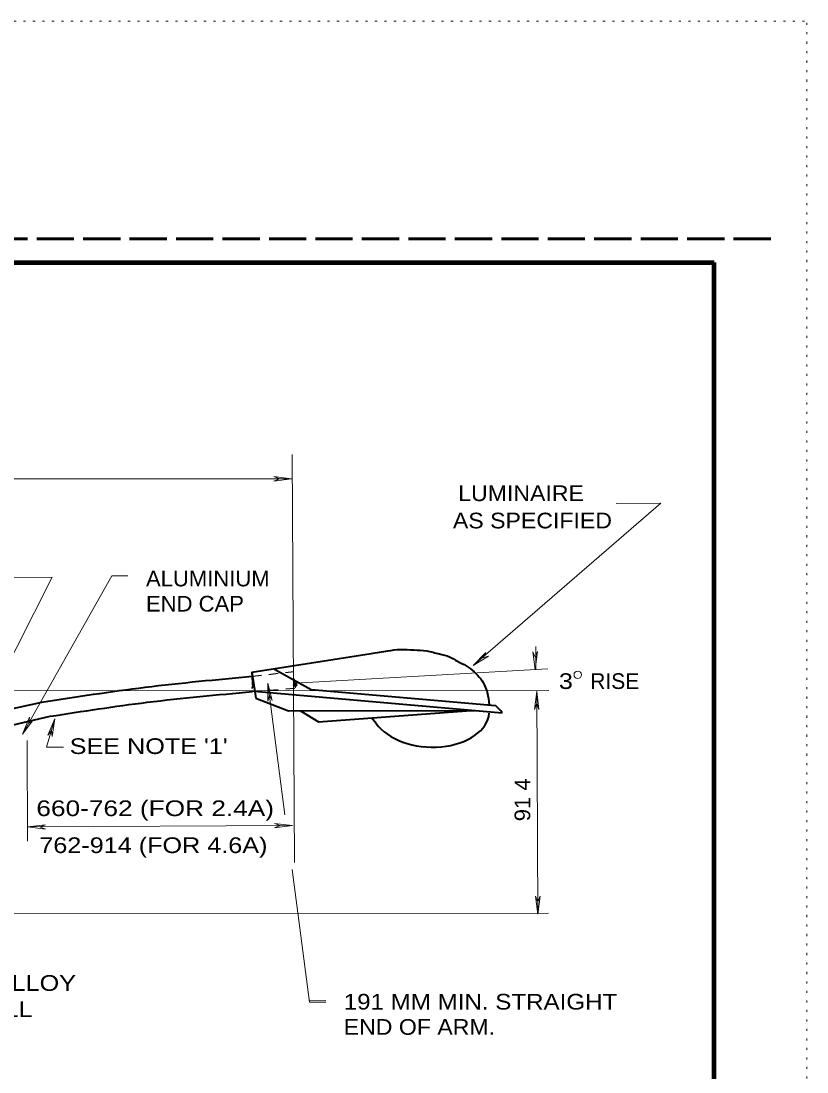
# Model space of a CAD drawing. Extents: x 312583 to 312854, y 144419 to 144597.
# Drawn here: x 312815.4 to 312853.5, y 144545.9 to 144596.8 of the extents above; entities that cross this region are included whole.
import ezdxf

# ---------------------------------------------------------------- set-up
doc = ezdxf.new("R2010")
doc.units = 0
doc.header["$LTSCALE"] = 0.3
doc.header["$PDMODE"] = 32
doc.header["$PDSIZE"] = 0.15
for name, pattern in [('DOTTED', [1.5, 0.3, -1.2]), ('LONG_DASHED', [7.5, 6, -1.5]), ('SHORT_DASHED', [2.7, 1.5, -1.2])]:
    doc.linetypes.add(name, pattern=pattern)
for name, color, linetype, lineweight in [('1', 7, 'Continuous', 35), ('2', 7, 'Continuous', 13), ('62', 7, 'DOTTED', 13), ('63', 7, 'LONG_DASHED', 60)]:
    doc.layers.add(name, color=color, linetype=linetype, lineweight=lineweight)

msp = doc.modelspace()

# ---------------------------------------------------------------- linework, layer by layer
at = {"layer": '1', "lineweight": 158}
msp.add_line((312849, 144423.1446), (312849, 144585.0846), dxfattribs=at)
at = {"layer": '1', "lineweight": 13}
msp.add_line((312840.3674, 144565.3613), (312840.3674, 144566.4806), dxfattribs=at)
at = {"layer": '1', "lineweight": 40}
for p, q in [((312826.6134, 144565.231), (312832.394, 144566.1356)), ((312826.6057, 144565.2233), (312826.6134, 144565.231)), ((312826.6134, 144565.231), (312826.667, 144564.495)), ((312826.6134, 144565.231), (312826.8127, 144563.966)), ((312827.7097, 144565.3843), (312829.4884, 144564.3876)), ((312826.6057, 144564.4873), (312826.667, 144564.495)), ((312829.4884, 144564.3876), (312838.4124, 144563.6133)), ((312826.7284, 144564.3033), (312838.742, 144563.2606)), ((312770.2404, 144553.754), (312816.4474, 144563.7743)), ((312813.166, 144562.2333), (312816.846, 144563.092))]:
    msp.add_line(p, q, dxfattribs=at)
at = {"layer": '1', "linetype": 'SHORT_DASHED', "lineweight": 25}
for p, q in [((312826.644, 144565.0316), (312828.645, 144565.2616)), ((312828.7294, 144564.4643), (312828.645, 144565.2616)), ((312826.644, 144564.288), (312828.7294, 144564.4643))]:
    msp.add_line(p, q, dxfattribs=at)
at = {"layer": '1', "lineweight": 158}
msp.add_lwpolyline([(312616.5, 144423.1446), (312616.5, 144585.0846), (312849, 144585.0846)], dxfattribs=at)
at = {"layer": '1', "lineweight": 40}
for points in [[(312826.8127, 144563.966), (312828.392, 144563.3526), (312837.408, 144563.3756)], [(312828.967, 144563.3526), (312829.8487, 144562.8313), (312837.017, 144563.3526)]]:
    msp.add_lwpolyline(points, dxfattribs=at)
msp.add_arc((312836.6357, 144561.6006), 2.6839, 38.22857, 48.47979, dxfattribs=at)
msp.add_ellipse((312835.2491, 144563.4306), major_axis=(-2.8667, 0.1434), ratio=0.637387, start_param=0.461652, end_param=3.1175647, dxfattribs=at)
for points in [[(312832.394, 144566.1356), (312833.2067, 144566.266), (312833.8047, 144566.335), (312834.464, 144566.312), (312835.085, 144566.266), (312835.6984, 144566.1126), (312836.189, 144565.9823), (312836.58, 144565.76), (312837.0017, 144565.5376), (312837.3774, 144565.254), (312837.707, 144564.9013), (312837.9064, 144564.5486), (312838.0137, 144564.2573), (312838.1134, 144563.644)], [(312816.4474, 144563.7743), (312821.4537, 144564.5026), (312826.644, 144565.0316)], [(312816.846, 144563.092), (312821.5534, 144563.7743), (312826.644, 144564.288)]]:
    msp.add_spline(points, degree=3, dxfattribs=at)
at = {"layer": '1'}
msp.add_point((312828.714, 144564.6176), dxfattribs=at)
at = {"layer": '2'}
for p, q in [((312828.6834, 144556.008), (312828.576, 144575.7803)), ((312828.5454, 144574.5996), (312769.2667, 144574.5843)), ((312827.679, 144574.707), (312827.955, 144574.5996)), ((312828.5454, 144574.5996), (312827.679, 144574.707)), ((312827.679, 144574.4923), (312827.955, 144574.5996)), ((312828.5454, 144574.5996), (312827.679, 144574.4923)), ((312846.4164, 144573.419), (312837.3314, 144565.5606)), ((312846.4164, 144573.419), (312844.2557, 144573.4032)), ((312816.9457, 144569.831), (312813.2657, 144562.5553)), ((312816.9457, 144569.831), (312814.0247, 144569.8156)), ((312819.836, 144569.8923), (312815.5197, 144562.2333)), ((312820.618, 144569.9), (312819.836, 144569.8923)), ((312837.3314, 144565.5606), (312837.9447, 144566.1816)), ((312837.3314, 144565.5606), (312838.075, 144566.013)), ((312837.9447, 144566.1816), (312837.7914, 144565.9286)), ((312838.075, 144566.013), (312837.7914, 144565.9286)), ((312840.2294, 144566.22), (312840.3444, 144565.9516)), ((312840.3444, 144565.3613), (312840.2294, 144566.22)), ((312840.444, 144566.2276), (312840.3444, 144565.9516)), ((312840.3444, 144565.3613), (312840.444, 144566.2276)), ((312840.9577, 144565.3996), (312828.7217, 144564.6943)), ((312828.2234, 144558.3233), (312827.3954, 144564.702)), ((312827.3954, 144564.702), (312827.3954, 144563.828)), ((312827.3954, 144564.702), (312827.61, 144563.851)), ((312840.996, 144564.3416), (312755.1677, 144564.311)), ((312827.3954, 144563.828), (312827.472, 144564.1116)), ((312827.61, 144563.851), (312827.472, 144564.1116)), ((312840.4134, 144564.2956), (312840.306, 144563.4293)), ((312840.4747, 144553.5086), (312840.4134, 144564.3263)), ((312840.4134, 144564.2956), (312840.5207, 144563.4293)), ((312840.306, 144563.4293), (312840.4134, 144563.7053)), ((312840.5207, 144563.4293), (312840.4134, 144563.7053)), ((312815.5197, 144562.2333), (312815.8494, 144563.046)), ((312815.5197, 144562.2333), (312816.041, 144562.9386)), ((312815.8494, 144563.046), (312815.811, 144562.7546)), ((312816.041, 144562.9386), (312815.811, 144562.7546)), ((312816.6774, 144561.5893), (312817.0837, 144562.977)), ((312817.0837, 144562.977), (312816.7387, 144562.1796)), ((312817.0837, 144562.977), (312816.7387, 144562.1796)), ((312817.0837, 144562.977), (312816.9457, 144562.1183)), ((312817.0837, 144562.977), (312816.9457, 144562.1183)), ((312816.7387, 144562.1796), (312816.9227, 144562.4096)), ((312816.7387, 144562.1796), (312816.9227, 144562.4096)), ((312816.9457, 144562.1183), (312816.9227, 144562.4096)), ((312816.9457, 144562.1183), (312816.9227, 144562.4096)), ((312815.7574, 144557.0353), (312815.7344, 144561.9266)), ((312817.4977, 144561.597), (312816.6774, 144561.5893)), ((312815.7574, 144557.733), (312816.6237, 144557.8403)), ((312815.7574, 144557.733), (312816.6237, 144557.8403)), ((312828.5837, 144557.802), (312815.7574, 144557.733)), ((312816.6237, 144557.8403), (312816.3477, 144557.733)), ((312816.6237, 144557.8403), (312816.3477, 144557.733)), ((312827.7097, 144557.9016), (312827.9934, 144557.802)), ((312828.5837, 144557.802), (312827.7097, 144557.9016)), ((312827.7174, 144557.687), (312827.9934, 144557.802)), ((312828.5837, 144557.802), (312827.7174, 144557.687)), ((312815.7574, 144557.733), (312816.6237, 144557.6256)), ((312815.7574, 144557.733), (312816.6237, 144557.6256)), ((312816.6237, 144557.6256), (312816.3477, 144557.733)), ((312816.6237, 144557.6256), (312816.3477, 144557.733)), ((312829.4117, 144549.2383), (312828.5684, 144555.6706)), ((312840.3597, 144554.375), (312840.467, 144554.099)), ((312840.4747, 144553.5086), (312840.3597, 144554.375)), ((312840.5744, 144554.375), (312840.467, 144554.099)), ((312840.4747, 144553.5086), (312840.5744, 144554.375)), ((312840.9884, 144553.547), (312779.5554, 144553.5316)), ((312830.1937, 144549.315), (312829.4117, 144549.3073)), ((312830.1937, 144549.246), (312829.4117, 144549.2383))]:
    msp.add_line(p, q, dxfattribs=at)
at = {"layer": '2', "lineweight": 40}
msp.add_line((312832.6394, 144562.747), (312832.417, 144563.0153), dxfattribs=at)
at = {"layer": '2'}
msp.add_circle((312842.3995, 144565.1056), 0.1797, dxfattribs=at)
at = {"layer": '62'}
msp.add_line((312601.2, 144596.7846), (312853.5, 144596.7846), dxfattribs=at)
msp.add_lwpolyline([(312601.2, 144418.5846), (312853.5, 144418.5846), (312853.5, 144596.7846)], dxfattribs=at)
at = {"layer": '63'}
msp.add_line((312851.75, 144586.2246), (312583.526, 144586.2246), dxfattribs=at)

# ---------------------------------------------------------------- texts
at = {"layer": '2'}
for s, width, p in [('LUMINAIRE ', 1.1, (312836.6118, 144573.5213)), ('AS SPECIFIED', 1.1, (312836.3544, 144572.1989)), ('ALUMINIUM', 1.05, (312821.4919, 144569.3892)), ('END CAP', 1.05, (312821.4919, 144568.1692)), ('3   ', 1.2, (312841.4867, 144564.4173)), ("SEE NOTE '1'", 1.2, (312817.7967, 144561.2663)), ('660-762 (FOR 2.4A)', 1.25, (312816.1829, 144558.2573)), ('762-914 (FOR 4.6A)', 1.2, (312816.3257, 144556.466)), ('6063-T6 ALUMINUM ALLOY', 1.2, (312802.4466, 144549.7894)), ('191 MM MIN. STRAIGHT', 1.15, (312831.067, 144548.881)), ('3 MM MIN. THICK WALL', 1.2, (312802.3766, 144548.5197)), ('END OF ARM.', 1.1, (312831.067, 144547.661))]:
    msp.add_text(s, height=0.76, dxfattribs=dict(at, width=width)).set_placement(p)
msp.add_text('RISE', height=0.76, dxfattribs=at).set_placement((312843.0047, 144564.4173))
at = {"layer": '2', "width": 1.05}
msp.add_text('91 4', height=0.76, rotation=90, dxfattribs=at).set_placement((312840.1005, 144558.0063))

doc.saveas('drawing.dxf')
